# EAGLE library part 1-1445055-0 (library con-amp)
Micro MATE-N-LOK Connectors grid 1.5 mm Source: ENG_CD_1445055_A.pdf
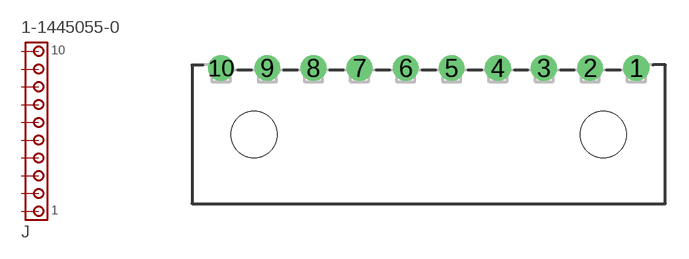
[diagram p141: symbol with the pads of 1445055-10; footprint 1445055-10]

Designator prefix J

## 1-1445055-0 (MF: TYCO ELECTRONICS; MPN: 1-1445055-0; OC_FARNELL: unknown; OC_NEWARK: 09H5353)  [1445055-10]
1  1  pas
2  2  pas
3  3  pas
4  4  pas
5  5  pas
6  6  pas
7  7  pas
8  8  pas
9  9  pas
10  10  pas

## Footprint 1445055-10 (pad centres in mm)
Micro MATE-N-LOK Connectors grid 3.0 mm Source: ENG_CD_1445055_A.pdf
drill 1 pad 1.676 round: 1 13.5,4.32; 2 10.5,4.32; 3 7.5,4.32; 4 4.5,4.32; 5 1.5,4.32; 6 -1.5,4.32; 7 -4.5,4.32; 8 -7.5,4.32; 9 -10.5,4.32; 10 -13.5,4.32
hole 3 at -11.35,0
hole 3 at 11.35,0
